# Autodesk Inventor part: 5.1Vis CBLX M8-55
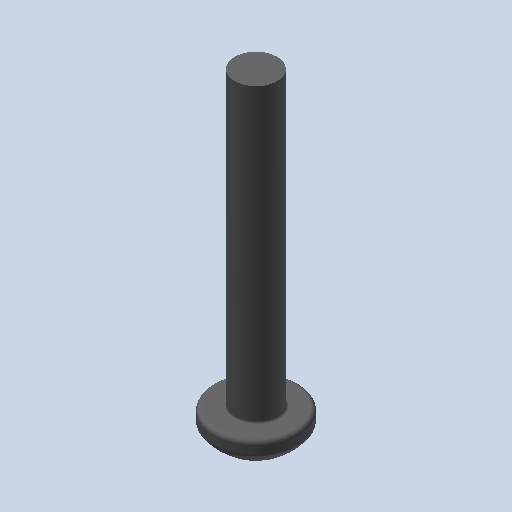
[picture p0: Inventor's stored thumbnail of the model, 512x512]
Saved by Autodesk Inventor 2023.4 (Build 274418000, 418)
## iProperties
Created: 2011-01
Part Number: 5.1Vis CBLX M8-55
Document SubType Name: Modeling
Designer: eric
Density: 1 g/cm^3
Mass: 3.64172 g
Surface Area: 20.0459 cm^2
Volume: 3.64172 cm^3
Material: Générique
Appearance: Red
Author: eric
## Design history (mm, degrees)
feature "Base1"
node "Corps solides"
node "Corps surfaciques"
node "Solide1"
